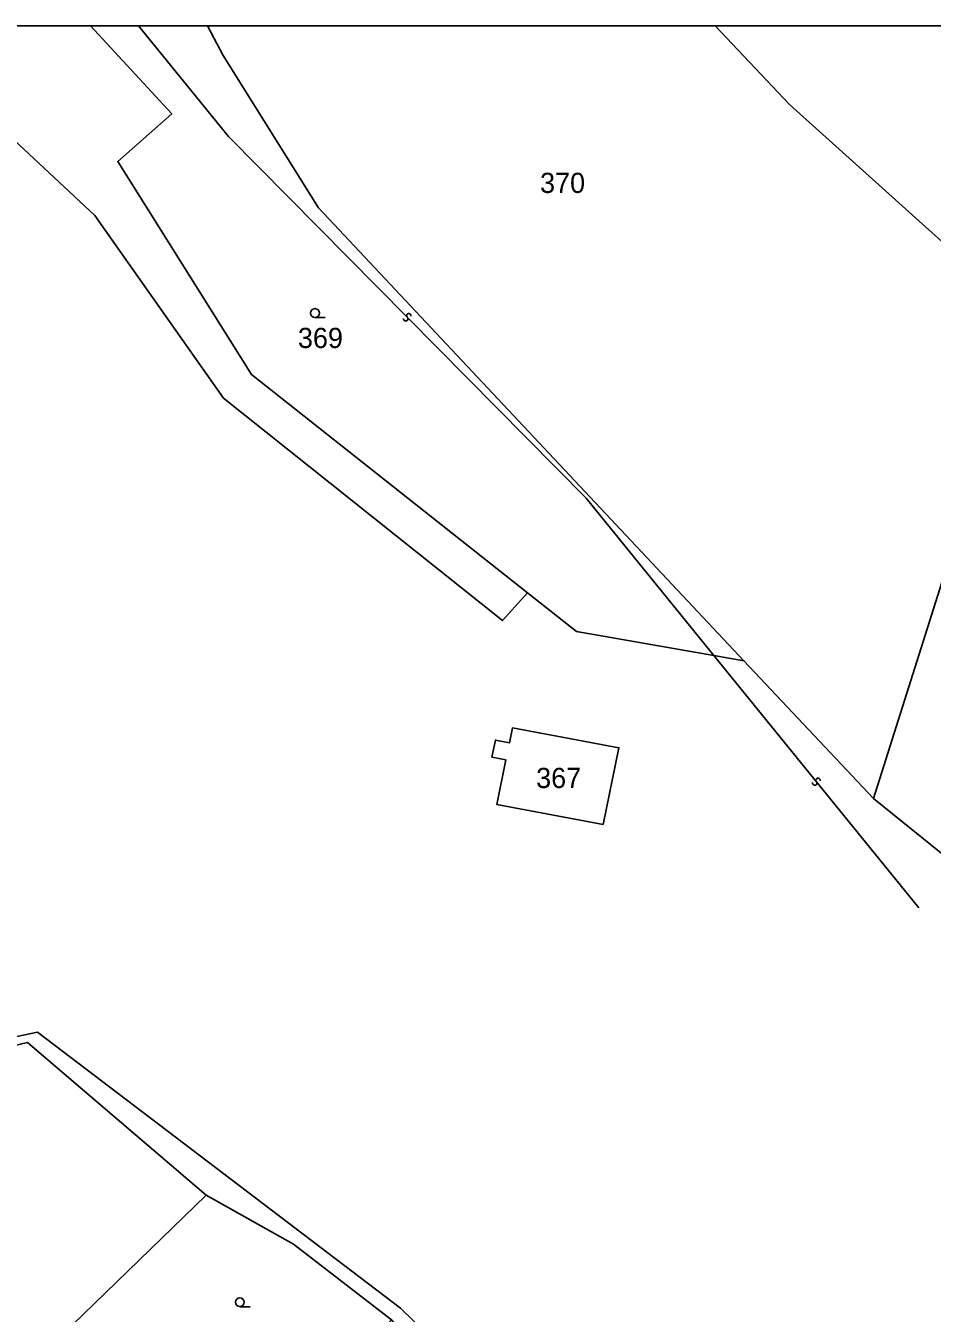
# Model space of a CAD drawing. Extents: x -598233 to -596890, y -1157848 to -1156431.
# Drawn here: x -597711.3 to -597635, y -1156539.3 to -1156430.9 of the extents above; entities that cross this region are included whole.
import ezdxf

# ---------------------------------------------------------------- set-up
doc = ezdxf.new("R2010")
doc.units = 0
for name, color, linetype in [('Level 1', 7, 'Continuous'), ('Level 13', 7, 'Continuous'), ('Level 3', 7, 'Continuous'), ('Level 4', 7, 'Continuous'), ('Level 5', 7, 'Continuous'), ('Level 60', 7, 'Continuous'), ('Vrstva 60', 7, 'Continuous'), ('zajmove_uzemi', 7, 'Continuous')]:
    doc.layers.add(name, color=color, linetype=linetype)

msp = doc.modelspace()

# ---------------------------------------------------------------- linework, layer by layer
at = {"layer": 'Level 1'}
for points in [[(-597802.33, -1156430.86), (-597801.88, -1156432.48), (-597791.08, -1156443.38), (-597776.99, -1156453.9), (-597771.76, -1156458.57), (-597758.28, -1156472.63), (-597740.15, -1156474.56), (-597730.72, -1156484.39), (-597733.33, -1156516.4), (-597728.53, -1156519.44), (-597710.3, -1156515.63), (-597679.72, -1156538.87), (-597674.19, -1156544.27), (-597669.38, -1156550.28), (-597660.84, -1156556.14)], [(-597669.04, -1156478.62), (-597671.13, -1156480.96), (-597694.63, -1156462.22), (-597705.48, -1156446.85), (-597722.59, -1156430.86)], [(-597705.82, -1156430.86), (-597698.99, -1156438.27), (-597703.54, -1156442.28), (-597692.28, -1156460.22), (-597669.04, -1156478.62)], [(-597650.81, -1156484.34), (-597686.64, -1156446.18), (-597694.67, -1156433.35), (-597695.98, -1156430.86)], [(-597653.23, -1156430.86), (-597646.98, -1156437.48), (-597633.03, -1156450.03), (-597629.42, -1156462.74)], [(-597632.42, -1156472.25), (-597639.9, -1156495.95)], [(-597669.04, -1156478.62), (-597664.9, -1156481.89), (-597653.34, -1156483.9)], [(-597653.34, -1156483.9), (-597650.81, -1156484.34)], [(-597639.9, -1156495.95), (-597650.81, -1156484.34)], [(-597661.34, -1156491.67), (-597662.67, -1156498.12), (-597671.63, -1156496.44), (-597670.86, -1156492.69), (-597672.03, -1156492.45), (-597671.74, -1156491.02), (-597670.56, -1156491.26), (-597670.3, -1156490), (-597661.34, -1156491.67)], [(-597639.9, -1156495.95), (-597612.57, -1156518), (-597608.92, -1156520.79)], [(-597733.74, -1156518.33), (-597730.43, -1156521.08), (-597711.14, -1156516.49), (-597696.1, -1156529.34)], [(-597696.1, -1156529.34), (-597714.93, -1156547.59)], [(-597696.1, -1156529.34), (-597688.75, -1156533.47), (-597680.48, -1156539.85)]]:
    msp.add_lwpolyline(points, dxfattribs=at)
at = {"layer": 'Level 13'}
for centre, start, end in [((-597679.29, -1156455.54), 171.8272, 44.4172), ((-597679.03, -1156455.28), 352.0417, 224.1397), ((-597644.85, -1156494.65), 166.243, 38.833), ((-597644.57, -1156494.42), 346.4575, 218.5555)]:
    msp.add_arc(centre, 0.184, start, end, dxfattribs=at)
at = {"layer": 'Level 3'}
for points in [[(-597701.79, -1156430.86), (-597694.22, -1156440.18), (-597664.11, -1156470.64), (-597653.34, -1156483.9)], [(-597653.34, -1156483.9), (-597636.08, -1156505.15)]]:
    msp.add_lwpolyline(points, dxfattribs=at)
at = {"layer": 'Level 5'}
for p, q in [((-597686.93, -1156455.44), (-597686.06, -1156455.44)), ((-597693.26, -1156538.75), (-597692.39, -1156538.75))]:
    msp.add_line(p, q, dxfattribs=at)
for centre in [(-597686.93, -1156455.06), (-597693.26, -1156538.37)]:
    msp.add_circle(centre, 0.375, dxfattribs=at)
at = {"layer": 'Level 60'}
msp.add_lwpolyline([(-597612.57, -1156518), (-597639.9, -1156495.95), (-597632.42, -1156472.25)], dxfattribs=at)
for points in [[(-597661.34, -1156491.67), (-597662.67, -1156498.12), (-597671.63, -1156496.44), (-597670.86, -1156492.69), (-597672.03, -1156492.45), (-597671.74, -1156491.02), (-597670.56, -1156491.26), (-597670.3, -1156490)], [(-597730.43, -1156521.08), (-597711.14, -1156516.49), (-597696.1, -1156529.34), (-597714.93, -1156547.59), (-597718.62, -1156551.17), (-597722.07, -1156554.54), (-597746.2, -1156531.73), (-597733.74, -1156518.33)], [(-597680.48, -1156539.85), (-597707.9, -1156569.74), (-597712.72, -1156565.44), (-597713.39, -1156564.76), (-597714.2, -1156563.54), (-597714.55, -1156562.38), (-597714.71, -1156560.96), (-597714.69, -1156560.53), (-597714.42, -1156559.32), (-597713.77, -1156557.82), (-597709.19, -1156552.96), (-597710.87, -1156551.39), (-597713.83, -1156548.62), (-597714.93, -1156547.59), (-597696.1, -1156529.34), (-597688.75, -1156533.47)]]:
    msp.add_lwpolyline(points, close=True, dxfattribs=at)
at = {"layer": 'Vrstva 60'}
for points in [[(-596983.04, -1156430.86), (-598045.83, -1156430.86)], [(-597728.53, -1156519.44), (-597710.3, -1156515.63), (-597679.72, -1156538.87), (-597674.19, -1156544.27), (-597669.38, -1156550.28), (-597660.84, -1156556.14), (-597633.83, -1156542.88), (-597622.74, -1156533.93), (-597608.92, -1156520.79), (-597612.57, -1156518), (-597639.9, -1156495.95), (-597650.81, -1156484.34), (-597653.34, -1156483.9), (-597664.9, -1156481.89), (-597669.04, -1156478.62), (-597671.13, -1156480.96), (-597694.63, -1156462.22), (-597705.48, -1156446.85), (-597722.59, -1156430.86)], [(-597730.43, -1156521.08), (-597711.14, -1156516.49), (-597696.1, -1156529.34), (-597688.75, -1156533.47), (-597680.48, -1156539.85), (-597670.88, -1156551.56), (-597667.84, -1156553.42), (-597662.26, -1156556.84), (-597660.84, -1156556.14), (-597669.38, -1156550.28), (-597674.19, -1156544.27), (-597679.72, -1156538.87), (-597710.3, -1156515.63), (-597728.53, -1156519.44)]]:
    msp.add_lwpolyline(points, dxfattribs=at)
for points in [[(-597705.82, -1156430.86), (-597722.59, -1156430.86), (-597705.48, -1156446.85), (-597694.63, -1156462.22), (-597671.13, -1156480.96), (-597669.04, -1156478.62), (-597692.28, -1156460.22), (-597703.54, -1156442.28), (-597698.99, -1156438.27)], [(-597695.98, -1156430.86), (-597705.82, -1156430.86), (-597698.99, -1156438.27), (-597703.54, -1156442.28), (-597692.28, -1156460.22), (-597669.04, -1156478.62), (-597664.9, -1156481.89), (-597653.34, -1156483.9), (-597650.81, -1156484.34), (-597686.64, -1156446.18), (-597694.67, -1156433.35)], [(-597653.23, -1156430.86), (-597695.98, -1156430.86), (-597694.67, -1156433.35), (-597686.64, -1156446.18), (-597650.81, -1156484.34), (-597639.9, -1156495.95), (-597632.42, -1156472.25), (-597629.42, -1156462.74), (-597633.03, -1156450.03), (-597646.98, -1156437.48)], [(-597614.08, -1156430.86), (-597653.23, -1156430.86), (-597646.98, -1156437.48), (-597633.03, -1156450.03), (-597629.42, -1156462.74), (-597620.19, -1156443.55)], [(-597671.63, -1156496.44), (-597670.86, -1156492.69), (-597672.03, -1156492.45), (-597671.74, -1156491.02), (-597670.56, -1156491.26), (-597670.3, -1156490), (-597661.34, -1156491.67), (-597662.67, -1156498.12)]]:
    msp.add_lwpolyline(points, close=True, dxfattribs=at)
at = {"layer": 'zajmove_uzemi'}
msp.add_lwpolyline([(-598232.89, -1156430.86), (-596890.46, -1156430.86), (-596890.46, -1157848.46), (-598232.89, -1157848.46)], close=True, dxfattribs=at)

# ---------------------------------------------------------------- texts
at = {"layer": 'Level 4'}
for s, p in [('370', (-597667.98, -1156444.94)), ('369', (-597688.37, -1156458)), ('367', (-597668.31, -1156495.06))]:
    msp.add_text(s, height=1.7, dxfattribs=at).set_placement(p)

doc.saveas('drawing.dxf')
